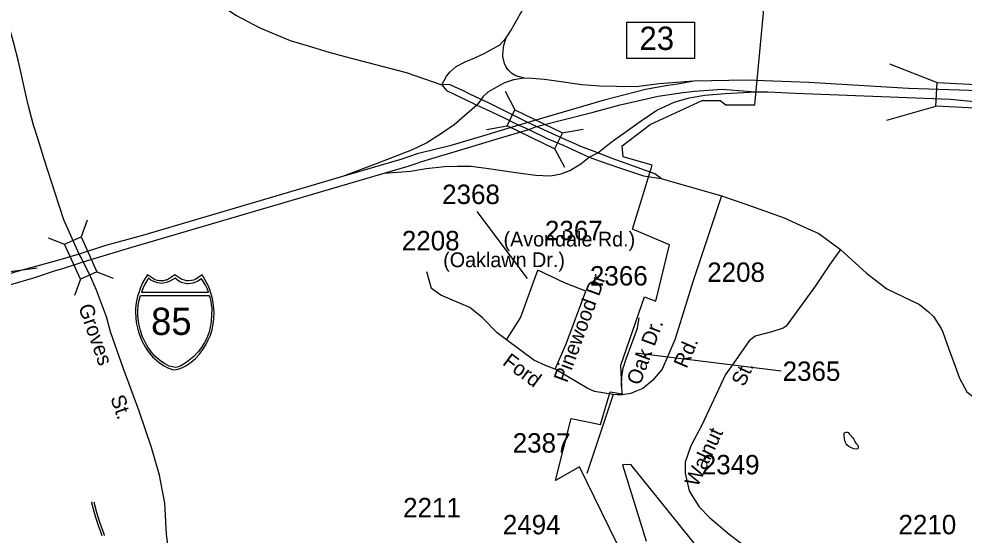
# Model space of a CAD drawing. Extents: x 1364363 to 1407445, y 538563 to 573342.
# Drawn here: x 1373269 to 1379352, y 554787 to 558110 of the extents above; entities that cross this region are included whole.
import ezdxf

# ---------------------------------------------------------------- set-up
doc = ezdxf.new("R2010")
doc.units = 0
for name, color, linetype in [('Exist Boundary Political City Limit New', 7, 'Continuous'), ('Exist Hydrographic Island Shore', 7, 'Continuous'), ('Exist Railroad Mainline', 7, 'Continuous'), ('Exist Railroad Siding', 7, 'Continuous'), ('Exist Road Primary Interstate Divided Center Attributed', 7, 'Continuous'), ('Exist Road Primary Interstate Interchange CELL', 7, 'Continuous'), ('Exist Road Primary Interstate Ramp 1 Lane Attributed', 7, 'Continuous'), ('Exist Road Primary Interstate Shield CELL', 7, 'Continuous'), ('Exist Road Primary Interstate Shield Number Label', 7, 'Continuous'), ('Exist Road Primary Interstate Structure Standard Bridge CELL', 7, 'Continuous'), ('Exist Road Primary NC Attributed', 7, 'Continuous'), ('Exist Road Primary NC Divided Attributed', 7, 'Continuous'), ('Exist Road Primary NC Structure Standard Bridge CELL', 7, 'Continuous'), ('Exist Road Secondary Structure Standard Bridge CELL', 7, 'Continuous'), ('Exist Road Secondary Type 51 Attributed', 7, 'Continuous'), ('Exist Road Secondary Type 51 Label', 7, 'Continuous'), ('Exist Road Secondary Type 51 Number Label', 7, 'Continuous')]:
    doc.layers.add(name, color=color, linetype=linetype)

msp = doc.modelspace()

# ---------------------------------------------------------------- linework, layer by layer
at = {"layer": 'Exist Boundary Political City Limit New'}
for points in [[(1377166, 554634.2), (1376876.8, 555225.4), (1376722.5, 555138.3), (1376823.6, 555536.9), (1377011.4, 555498.3), (1377074.1, 555708.3), (1377150.8, 555696.2), (1377142.6, 555881.8), (1377295.8, 556321.4), (1377368.2, 556293.2), (1377456.9, 556656.2), (1377219.2, 556757), (1377344.1, 557168.4), (1377158.8, 557220.9), (1377150.8, 557293.5), (1377332, 557430.6), (1377666.4, 557583.9), (1377783.2, 557583.9), (1377819.5, 557555.7), (1378004.9, 557555.7), (1378108.8, 558650.4)], [(1377784.9, 554525.8), (1377207.1, 555240.4), (1377154.8, 555239.6), (1377305.8, 554748.8)]]:
    msp.add_lwpolyline(points, dxfattribs=at)
at = {"layer": 'Exist Hydrographic Island Shore'}
msp.add_lwpolyline([(1378614.7, 555436.1), (1378635.8, 555413.3), (1378642.1, 555404.6), (1378645.3, 555398), (1378648.3, 555388.7), (1378655.2, 555378.7), (1378667.4, 555366.6), (1378670.5, 555358.7), (1378670.9, 555348.2), (1378667.5, 555341.8), (1378657, 555340.7), (1378642.6, 555342.4), (1378630.9, 555345.9), (1378610.8, 555357.6), (1378600, 555366.3), (1378593.6, 555375), (1378587.4, 555387.6), (1378582.5, 555406.7), (1378581.1, 555427.1), (1378580.8, 555441.5), (1378583.6, 555447.3), (1378592.1, 555450.4), (1378599.4, 555450.2), (1378605.8, 555448), (1378614.7, 555436.1)], dxfattribs=at)
at = {"layer": 'Exist Railroad Mainline'}
for points in [[(1373791, 554820.3), (1373790.4, 554822.1), (1373789.8, 554823.9), (1373789, 554825.7), (1373788.4, 554827.5), (1373787.8, 554829.3), (1373787.1, 554831.1), (1373786.5, 554832.9), (1373785.9, 554834.7), (1373785.3, 554836.5), (1373784.7, 554838.3), (1373784, 554840.1), (1373783.3, 554841.9), (1373782.7, 554843.7), (1373782.1, 554845.5), (1373781.5, 554847.3), (1373780.9, 554849.1), (1373780.3, 554850.9), (1373779.7, 554852.7), (1373779, 554854.6), (1373778.5, 554856.4), (1373777.9, 554858.2), (1373777.3, 554860), (1373776.6, 554861.8), (1373776, 554863.6), (1373775.3, 554865.5), (1373774.8, 554867.2), (1373774.2, 554869), (1373773.6, 554870.9), (1373773, 554872.7), (1373772.5, 554874.5), (1373771.9, 554876.3), (1373771.2, 554878.1), (1373770.7, 554880), (1373770.1, 554881.8), (1373769.6, 554883.5), (1373769, 554885.4), (1373768.4, 554887.2), (1373767.9, 554889.1), (1373767.2, 554890.9), (1373766.7, 554892.7), (1373766.1, 554894.5), (1373765.6, 554896.3), (1373765, 554898.1), (1373764.5, 554900), (1373763.9, 554901.8), (1373763.3, 554903.6), (1373762.7, 554905.4), (1373762.2, 554907.3), (1373761.7, 554909.1), (1373761.1, 554910.9), (1373760.6, 554912.8), (1373760.2, 554914.6), (1373759.5, 554916.5), (1373759, 554918.3), (1373758.5, 554920.2), (1373757.9, 554921.9), (1373757.4, 554923.7), (1373756.9, 554925.6), (1373756.4, 554927.4), (1373755.9, 554929.3), (1373755.2, 554931.1), (1373754.7, 554932.9), (1373754.2, 554934.8), (1373753.7, 554936.6), (1373753.2, 554938.5), (1373752.8, 554940.3), (1373752.3, 554942.1), (1373751.8, 554943.9), (1373751.3, 554945.8), (1373750.7, 554947.6), (1373750.2, 554949.5), (1373749.7, 554951.3), (1373749.2, 554953.2), (1373748.8, 554955), (1373748.3, 554956.9), (1373747.8, 554958.7), (1373747.3, 554960.5), (1373746.7, 554962.4), (1373746.2, 554964.2), (1373745.7, 554966.1), (1373745.2, 554967.9), (1373744.8, 554969.8), (1373744.4, 554971.6), (1373743.9, 554973.5), (1373743.4, 554975.3), (1373742.8, 554977.2), (1373742.5, 554979), (1373742, 554980.9), (1373741.5, 554982.7), (1373741, 554984.6), (1373740.6, 554986.4), (1373740.1, 554988.3), (1373739.7, 554990.1), (1373739.3, 554992), (1373738.7, 554993.9), (1373738.3, 554995.7), (1373737.9, 554997.6), (1373737.5, 554999.5), (1373737, 555001.2)], [(1373805.8, 554782.3), (1373803.2, 554788.6), (1373800.8, 554794.9), (1373798.2, 554801.3), (1373795.7, 554807.6), (1373793.4, 554813.9), (1373791, 554820.3)]]:
    msp.add_lwpolyline(points, dxfattribs=at)
at = {"layer": 'Exist Railroad Siding'}
for points in [[(1373751.5, 554999.7), (1373752, 554997.9), (1373752.4, 554996), (1373752.9, 554994.1), (1373753.2, 554992.2), (1373753.7, 554990.4), (1373754.1, 554988.5), (1373754.6, 554986.7), (1373755.1, 554984.8), (1373755.5, 554982.9), (1373756, 554981.1), (1373756.5, 554979.3), (1373756.9, 554977.4), (1373757.4, 554975.5), (1373757.9, 554973.6), (1373758.2, 554971.8), (1373758.7, 554969.9), (1373759.2, 554968.1), (1373759.8, 554966.2), (1373760.3, 554964.4), (1373760.8, 554962.5), (1373761.3, 554960.7), (1373761.6, 554958.8), (1373762.1, 554957), (1373762.6, 554955.1), (1373763.1, 554953.3), (1373763.7, 554951.4), (1373764.2, 554949.6), (1373764.6, 554947.7), (1373765.1, 554945.9), (1373765.7, 554944), (1373766.2, 554942.2), (1373766.7, 554940.3), (1373767.2, 554938.5), (1373767.8, 554936.6), (1373768.3, 554934.8), (1373768.8, 554932.9), (1373769.4, 554931.1), (1373769.9, 554929.3), (1373770.4, 554927.4), (1373770.8, 554925.6), (1373771.6, 554923.7), (1373772, 554921.9), (1373772.5, 554920), (1373773.1, 554918.3), (1373773.6, 554916.4), (1373774.2, 554914.6), (1373774.7, 554912.8), (1373775.2, 554910.9), (1373775.9, 554909.1), (1373776.4, 554907.2), (1373777, 554905.4), (1373777.5, 554903.5), (1373778.1, 554901.7), (1373778.7, 554900), (1373779.2, 554898.1), (1373779.9, 554896.3), (1373780.4, 554894.4), (1373781, 554892.6), (1373781.6, 554890.7), (1373782.1, 554888.9), (1373782.7, 554887.1), (1373783.3, 554885.3), (1373784, 554883.5), (1373784.5, 554881.7), (1373785.1, 554879.9), (1373785.7, 554878), (1373786.4, 554876.2), (1373787, 554874.4), (1373787.5, 554872.6), (1373788.2, 554870.7), (1373788.8, 554868.9), (1373789.4, 554867.1), (1373790, 554865.3), (1373790.6, 554863.5), (1373791.2, 554861.7), (1373791.9, 554859.9), (1373792.5, 554858.1), (1373793.1, 554856.2), (1373793.8, 554854.4), (1373794.4, 554852.6), (1373795, 554850.8), (1373795.7, 554849), (1373796.4, 554847.3), (1373797, 554845.5), (1373797.6, 554843.6), (1373798.2, 554841.8), (1373798.9, 554840), (1373799.6, 554838.2), (1373800.3, 554836.4), (1373800.9, 554834.6), (1373801.6, 554832.8), (1373802.2, 554831), (1373802.9, 554829.3), (1373803.6, 554827.4), (1373804.3, 554825.6), (1373804.9, 554823.9), (1373805.6, 554822.1), (1373806.2, 554820.2), (1373807, 554818.5)], [(1373807, 554818.5), (1373807.7, 554816.2), (1373808.7, 554814), (1373809.4, 554811.7), (1373810.2, 554809.5), (1373811, 554807.3), (1373811.8, 554805.1), (1373812.7, 554802.8), (1373813.5, 554800.6), (1373814.4, 554798.3), (1373815.1, 554796.1), (1373816, 554793.9), (1373816.9, 554791.6), (1373817.8, 554789.4), (1373818.6, 554787.2), (1373819.3, 554784.9)]]:
    msp.add_lwpolyline(points, dxfattribs=at)
at = {"layer": 'Exist Road Primary Interstate Divided Center Attributed'}
for points in [[(1377613, 557708.6), (1377510, 557689.5), (1377444.7, 557681), (1377302.9, 557654.5), (1377035.1, 557586.3), (1376545.3, 557441.9)], [(1376600.1, 557416.3), (1376964.8, 557508.7), (1377139.7, 557556.9), (1377383.3, 557611.9), (1377541.2, 557635.6), (1377617.8, 557645), (1377794.8, 557657.9), (1378009.8, 557639.5)], [(1382578.3, 557543.3), (1378993.5, 557662), (1378353.6, 557700.7), (1377951.9, 557715.7), (1377613, 557708.6)], [(1378009.8, 557639.5), (1378088.7, 557639.5), (1378267.6, 557630.8), (1379261.7, 557592.6), (1379417.1, 557579), (1379642.8, 557567.9)], [(1376487.2, 557426), (1376237.4, 557350.6), (1376043.1, 557293.6), (1375832.5, 557241.7), (1375732.8, 557206.1), (1375352.7, 557094.5)], [(1376545.3, 557441.9), (1376487.2, 557426)], [(1376551, 557397.1), (1376600.1, 557416.3)], [(1375618.9, 557117.1), (1375773.7, 557162.7), (1375826.7, 557179.5), (1375862.3, 557190.7), (1376155.6, 557280.6), (1376347.3, 557337.6), (1376551, 557397.1)], [(1373683.1, 556546.7), (1373833.5, 556591.3), (1373990.1, 556637.4), (1375618.9, 557117.1)], [(1375352.7, 557094.5), (1374063.5, 556716.3), (1373819.2, 556649.4), (1373657.6, 556595.2)], [(1373657.6, 556595.2), (1373518, 556555.5), (1373494.5, 556548.3)], [(1373494.5, 556548.3), (1373361.4, 556510.6), (1373243.1, 556479.9), (1372998.8, 556399.9), (1372757.8, 556335.3), (1372548.6, 556305.7), (1372327.4, 556284.9), (1371983.2, 556294.3), (1371870.2, 556305.5), (1371666.9, 556337.7)], [(1373503.6, 556489.2), (1373545.6, 556501.1), (1373683.1, 556546.7)], [(1371653, 556282.3), (1371856.4, 556250.9), (1372122.4, 556230.2), (1372326.3, 556232.5), (1372547, 556244.3), (1372777.5, 556281.7), (1373006.5, 556339.7), (1373216.8, 556401), (1373371.2, 556446), (1373503.6, 556489.2)]]:
    msp.add_lwpolyline(points, dxfattribs=at)
at = {"layer": 'Exist Road Primary Interstate Interchange CELL'}
msp.add_lwpolyline([(1377181.4, 558088.2), (1377616.3, 558088.2), (1377616.3, 557854.9), (1377181.4, 557854.9)], close=True, dxfattribs=at)
at = {"layer": 'Exist Road Primary Interstate Ramp 1 Lane Attributed'}
for points in [[(1376522.7, 557728.1), (1376468.2, 557744.1), (1376441.4, 557758), (1376420.5, 557779), (1376404.2, 557800), (1376393.7, 557823.3), (1376384.4, 557867.6), (1376385.5, 557907.2), (1376389, 557941), (1376405.3, 557988.8)], [(1376522.7, 557728.1), (1376452.6, 557717.7), (1376395, 557698.5), (1376346.7, 557672.9), (1376288, 557638.6), (1376254.4, 557607.8), (1376243.3, 557590.9)], [(1377613, 557708.6), (1377390.2, 557692.2), (1377241.8, 557673.3), (1377114.4, 557674.5), (1377007.8, 557677.5), (1376892.9, 557685.6), (1376759.8, 557703.7), (1376651.2, 557719.2), (1376570, 557725.8), (1376522.7, 557728.1)], [(1376994.3, 557247), (1377069.6, 557306.6), (1377110.5, 557337.1), (1377274.9, 557454.4), (1377373.8, 557522), (1377487.3, 557573.1), (1377581.8, 557600.5), (1377684.2, 557619.7), (1377813.7, 557629.6), (1378009.8, 557639.5)], [(1376216.8, 557554.6), (1376152.5, 557499.2), (1376071.3, 557428.3), (1375982.2, 557366.8), (1375894.6, 557311.4), (1375795.6, 557265.7), (1375672.7, 557218.1), (1375567.9, 557175.9), (1375352.7, 557094.5)], [(1376243.3, 557590.9), (1376216.8, 557554.6)], [(1376939.4, 557219.2), (1376994.3, 557247)], [(1375618.9, 557117.1), (1375790.1, 557129.4), (1375890.6, 557146.1), (1376007.6, 557160.2), (1376089.8, 557161.7), (1376179.4, 557161.4), (1376292.1, 557146.1), (1376452.1, 557124), (1376594.1, 557103.6), (1376690.3, 557099.8), (1376760.1, 557111.9), (1376815.7, 557132.9), (1376885.7, 557176), (1376939.4, 557219.2)], [(1373195.7, 556481.8), (1373385.8, 556508.1)]]:
    msp.add_lwpolyline(points, dxfattribs=at)
at = {"layer": 'Exist Road Primary Interstate Shield CELL'}
for points in [[(1374272.9, 555851.6), (1374282.4, 555852.5), (1374295.1, 555855), (1374307.5, 555859.1), (1374321.6, 555865.3), (1374342.4, 555876.9), (1374359.2, 555886.7), (1374378.5, 555899.7), (1374404.6, 555923.4), (1374430.7, 555950.8), (1374453.7, 555981.8), (1374471.9, 556010.8), (1374488, 556044), (1374501.4, 556074.9), (1374512.1, 556110.2), (1374519.2, 556144.5), (1374522.7, 556180.2), (1374525.1, 556219.7), (1374522.4, 556264.3), (1374514.7, 556309.8), (1374507.4, 556338.2), (1374496.4, 556372.1), (1374487.4, 556393.8), (1374466.6, 556432.2), (1374447.8, 556461.8), (1374420.6, 556442.7), (1374402.8, 556433.2), (1374392, 556428.4), (1374380.8, 556426.2), (1374360.3, 556423.7), (1374347.4, 556424.3), (1374335.5, 556427), (1374325.4, 556429.2), (1374317.1, 556433.2), (1374272.9, 556461.8), (1374228.6, 556433.2), (1374219.3, 556429), (1374209.8, 556427), (1374200.7, 556424.5), (1374185.5, 556423.7), (1374174, 556424.1), (1374162.1, 556426.2), (1374152.7, 556428.2), (1374142.2, 556433.2), (1374097.1, 556461.8), (1374079.4, 556436.1), (1374064.9, 556410.7), (1374049.5, 556374.8), (1374040, 556347), (1374033.2, 556324.1), (1374024.8, 556282.1), (1374020.5, 556245.6), (1374019.8, 556219.7), (1374024.5, 556155.2), (1374031.6, 556120.9), (1374038.8, 556093.1), (1374062.7, 556033), (1374080.6, 555999.4), (1374096, 555975.3), (1374117.6, 555948.1), (1374129.3, 555935.1), (1374174.1, 555896), (1374204, 555875.5), (1374227.9, 555862.6), (1374239.1, 555858.3), (1374256.7, 555853.4)], [(1374102.5, 556441.1), (1374091.5, 556424.2), (1374078.8, 556401.3), (1374068.7, 556377.7), (1374058.3, 556351.5), (1374489.9, 556351.4), (1374479.8, 556373.8), (1374469, 556396.3), (1374457.8, 556416.9), (1374444.1, 556436.8), (1374419.9, 556421.5), (1374402.3, 556413.2), (1374388.1, 556408.3), (1374376.1, 556405.6), (1374357.5, 556404.1), (1374349.2, 556404.6), (1374323.2, 556410.5), (1374305.7, 556417.7), (1374289, 556428.8), (1374275.5, 556441.5), (1374241.3, 556420.9), (1374226.1, 556414.2), (1374208.7, 556409.7), (1374189.6, 556407.3), (1374160.1, 556410.5), (1374137.1, 556418.5), (1374117.2, 556428.8)], [(1374492.4, 556330.1), (1374497, 556317.9), (1374503.4, 556290.8), (1374506.7, 556270), (1374510.1, 556246), (1374509, 556204.9), (1374507, 556162.3), (1374503.1, 556137.1), (1374497.8, 556114.1), (1374490.7, 556088.7), (1374479.1, 556054.8), (1374463.2, 556026.2), (1374443.3, 555994.4), (1374421.9, 555966.5), (1374412.5, 555954.9), (1374394.8, 555936.3), (1374362.6, 555910.4), (1374339.1, 555892.8), (1374310.9, 555876.2), (1374296.6, 555869.8), (1374279.9, 555866.3), (1374266.2, 555867.3), (1374249.6, 555871.7), (1374236.2, 555875.4), (1374206.7, 555891.3), (1374182.9, 555907.2), (1374143.1, 555939.8), (1374121.7, 555965), (1374101.6, 555994.3), (1374083.7, 556024.4), (1374064.7, 556064.1), (1374051.2, 556104), (1374041.4, 556147.1), (1374034.8, 556199.7), (1374034.1, 556231.8), (1374036, 556262.6), (1374039, 556278.8), (1374042.9, 556298.9), (1374050.8, 556329.8)]]:
    msp.add_lwpolyline(points, close=True, dxfattribs=at)
at = {"layer": 'Exist Road Primary Interstate Structure Standard Bridge CELL'}
for p, q in [((1378872.9, 557819.8), (1379178.3, 557699.3)), ((1378854.7, 557458.3), (1379170.7, 557547.5))]:
    msp.add_line(p, q, dxfattribs=at)
msp.add_lwpolyline([(1379178.3, 557699.3), (1380140.6, 557650.9), (1380133, 557499.1), (1379170.7, 557547.5)], close=True, dxfattribs=at)
at = {"layer": 'Exist Road Primary NC Attributed'}
for points in [[(1373393.2, 559110.3), (1373546.4, 558927.5), (1373672.9, 558788.1), (1373754, 558728.4), (1374002.3, 558569.7), (1374174.3, 558459.3), (1374317.1, 558365.2), (1374417.7, 558303.5), (1374665.6, 558134.4), (1374818.9, 558051.3), (1375015.6, 557971.4), (1375152.5, 557929.2), (1375263.7, 557895), (1375375.2, 557864.7), (1375761.2, 557763.7), (1375991.6, 557684.7)], [(1377401.7, 557083.3), (1377438.1, 557070.9), (1377789.9, 556970.1)], [(1377789.9, 556970.1), (1377948.1, 556916.8), (1378194.7, 556830.1), (1378349.5, 556759.3), (1378417.5, 556728), (1378556.6, 556624.7)], [(1378556.6, 556624.7), (1378724.3, 556474), (1378855.3, 556373), (1379065.3, 556270.3), (1379122.6, 556225.1), (1379155.8, 556194.9), (1379204.1, 556117.9), (1379216.1, 556093.7), (1379252.3, 555991.1), (1379294.6, 555873.4), (1379323.2, 555796.4), (1379369.7, 555708.2), (1379419.5, 555670.5), (1379517.6, 555637.3), (1379771, 555619.2), (1379885.7, 555608.6), (1380262.7, 555583.5)]]:
    msp.add_lwpolyline(points, dxfattribs=at)
at = {"layer": 'Exist Road Primary NC Divided Attributed'}
for points in [[(1376243.3, 557590.9), (1376167.3, 557626.8), (1376129.6, 557646.3), (1376038.1, 557687.6), (1375991.6, 557684.7)], [(1375991.6, 557684.7), (1376020.4, 557648.5), (1376119.4, 557601.4), (1376216.8, 557554.6)], [(1376216.8, 557554.6), (1376273.6, 557528), (1376392.5, 557472.2), (1376487.2, 557426)], [(1376545.3, 557441.9), (1376291.8, 557569.8), (1376243.3, 557590.9)], [(1376487.2, 557426), (1376527.4, 557407.7), (1376551, 557397.1)], [(1376600.1, 557416.3), (1376545.3, 557441.9)], [(1376994.3, 557247), (1376885.4, 557288.7), (1376833.7, 557311.8), (1376792.6, 557328.2), (1376600.1, 557416.3)], [(1376551, 557397.1), (1376668.7, 557340.5), (1376772.7, 557296.2), (1376939.4, 557219.2)], [(1377401.7, 557083.3), (1377362.3, 557112.3), (1377087.4, 557211.2), (1376994.3, 557247)], [(1376939.4, 557219.2), (1377009.7, 557194.4), (1377135.1, 557151), (1377289.4, 557099.8), (1377401.7, 557083.3)]]:
    msp.add_lwpolyline(points, dxfattribs=at)
at = {"layer": 'Exist Road Primary NC Structure Standard Bridge CELL'}
for p, q in [((1376398.1, 557645.1), (1376461.6, 557525.2)), ((1376277.5, 557397), (1376411, 557421.1)), ((1376766.5, 557376.4), (1376899.9, 557400.5)), ((1376717, 557274.6), (1376780.5, 557154.8))]:
    msp.add_line(p, q, dxfattribs=at)
msp.add_lwpolyline([(1376461.6, 557525.2), (1376766.7, 557376.9), (1376716.1, 557272.8), (1376411, 557421.1)], close=True, dxfattribs=at)
at = {"layer": 'Exist Road Secondary Structure Standard Bridge CELL'}
for p, q in [((1373709.2, 556813.6), (1373668.9, 556707.9)), ((1373457.5, 556700.9), (1373563.2, 556660.5)), ((1373769.7, 556481.4), (1373875.5, 556441.1)), ((1373666.4, 556435.2), (1373626.1, 556329.4))]:
    msp.add_line(p, q, dxfattribs=at)
msp.add_lwpolyline([(1373668.9, 556707.9), (1373770.2, 556481.6), (1373664.5, 556434.3), (1373563.2, 556660.5)], close=True, dxfattribs=at)
at = {"layer": 'Exist Road Secondary Type 51 Attributed'}
msp.add_line((1377093, 555692.2), (1376924.8, 555182.9), dxfattribs=at)
for points in [[(1376405.3, 557988.8), (1376432.1, 558030.8), (1376578.3, 558290.6), (1376705.4, 558504.3), (1376754.1, 558575.7), (1376780.1, 558630.9), (1376800.9, 558696.9), (1376784.7, 558778.1), (1376735.3, 558884.9), (1376715.3, 558959.2), (1376701.8, 559033), (1376699.8, 559125.4), (1376715.3, 559193.5), (1376760.6, 559280.3), (1376786.6, 559322.5)], [(1373657.6, 556595.2), (1373558.1, 556816.9), (1373503.2, 556988), (1373434.5, 557200), (1373394.2, 557327.6), (1373364, 557425.9), (1373326.7, 557565.7), (1373265.5, 557834.4), (1373234, 557959.1), (1373185.8, 558138.3), (1373119, 558331.9), (1372877, 558596.9)], [(1375991.6, 557684.7), (1376021, 557740.6), (1376045.4, 557769.7), (1376083.9, 557803.5), (1376140.9, 557832.6), (1376202.7, 557858.3), (1376263.2, 557886.3), (1376363.4, 557943.4), (1376385.5, 557966.7), (1376405.3, 557988.8)], [(1377789.9, 556970.1), (1377606.2, 556416.4), (1377525.1, 556153.4), (1377490.7, 556044.3), (1377409, 555854.7), (1377346.6, 555782), (1377284.3, 555731.3), (1377241.5, 555714.4), (1377206.5, 555698.8), (1377153.7, 555689.8)], [(1378556.6, 556624.7), (1378487, 556527.5), (1378396.2, 556391.2), (1378206.6, 556131), (1378187.1, 556118), (1378115.7, 556094.9), (1378008.4, 556068.3), (1377969.1, 556036.8), (1377866.7, 555889.8), (1377816.9, 555821.6), (1377664.7, 555494.3), (1377593.3, 555361.2), (1377557.6, 555257.3), (1377557.6, 555185.9), (1377583.5, 555072.2), (1377601.8, 555039.2), (1377646.2, 554970), (1377712.8, 554900.7), (1377840.7, 554794), (1377964.9, 554699.3)], [(1373683.1, 556546.7), (1373668.7, 556573.8), (1373657.6, 556595.2)], [(1374259.2, 554489.2), (1374251.6, 554550.6), (1374219.1, 554794.1), (1374209, 554993.4), (1374174.8, 555172.2), (1374122.3, 555351.5), (1374043.2, 555585.2), (1373941, 555863.4), (1373861.7, 556089.1), (1373833.5, 556191.4), (1373768.6, 556362.5), (1373722.7, 556466.2), (1373683.1, 556546.7)], [(1376407.6, 556043.9), (1376347.2, 556088.8), (1376253.1, 556186.2), (1376172, 556251.1), (1376074.6, 556293.3), (1375983.8, 556332.3), (1375925.3, 556374.5), (1375893.8, 556481.1)], [(1376407.6, 556043.9), (1376496.5, 556186.2), (1376608.1, 556492)], [(1376917, 556356.9), (1376780.7, 556411.5), (1376608.1, 556492)], [(1376720.4, 555855), (1376791.8, 556017.3), (1376917, 556356.9)], [(1377153.7, 555689.8), (1377148.1, 555749.5), (1377149.4, 555805.3), (1377157.1, 555862.5), (1377177.9, 555922.2), (1377250.6, 556118.3), (1377261, 556184.5)], [(1376720.4, 555855), (1376658.7, 555877.7), (1376584.1, 555913.4), (1376407.6, 556043.9)], [(1377093, 555692.2), (1376972.8, 555711.8), (1376926.1, 555732.6), (1376720.4, 555855)], [(1377153.7, 555689.8), (1377119.5, 555689.8), (1377093, 555692.2)]]:
    msp.add_lwpolyline(points, dxfattribs=at)
at = {"layer": 'Exist Road Secondary Type 51 Number Label'}
for p, q in [((1376543.4, 556437.9), (1376218.2, 556869.9)), ((1377239.7, 555960.2), (1378174.7, 555843.3))]:
    msp.add_line(p, q, dxfattribs=at)

# ---------------------------------------------------------------- texts
at = {"layer": 'Exist Road Primary Interstate Interchange CELL'}
msp.add_text('23', height=150, dxfattribs=at).set_placement((1377262.8, 557909.8))
at = {"layer": 'Exist Road Primary Interstate Shield Number Label'}
msp.add_text('85', height=175, dxfattribs=at).set_placement((1374120, 556075.4))
at = {"layer": 'Exist Road Secondary Type 51 Label'}
for s, p in [('(Avondale Rd.)', (1376388.1, 556644.7)), ('(Oaklawn Dr.)', (1375999.7, 556511.7))]:
    msp.add_text(s, height=95, dxfattribs=at).set_placement(p)
for s, rotation, p in [('Pinewood Dr.', 69.75451, (1376796.6, 555763)), ('Groves      St.', 289.35754, (1373650, 556256.5)), ('Oak Dr.', 69.66206, (1377266.3, 555745.7)), ('Rd.', 66.67043, (1377566, 555854.7)), ('Ford', 323.52921, (1376375.9, 555888)), ('Walnut         St.', 65.05389, (1377636.2, 555091.1))]:
    msp.add_text(s, height=95, rotation=rotation, dxfattribs=at).set_placement(p)
at = {"layer": 'Exist Road Secondary Type 51 Number Label'}
for s, p in [('2368', (1375993, 556918)), ('2367', (1376654.5, 556685.1)), ('2208', (1375733.7, 556619.9)), ('2366', (1376944.3, 556393.5)), ('2208', (1377699, 556416.7)), ('2365', (1378184.4, 555779.6)), ('2387', (1376447.2, 555317.9)), ('2349', (1377664.1, 555178.1)), ('2211', (1375741.7, 554901.6)), ('2494', (1376383.5, 554791.9)), ('2210', (1378929.9, 554792.3))]:
    msp.add_text(s, height=125, dxfattribs=at).set_placement(p)

doc.saveas('drawing.dxf')
